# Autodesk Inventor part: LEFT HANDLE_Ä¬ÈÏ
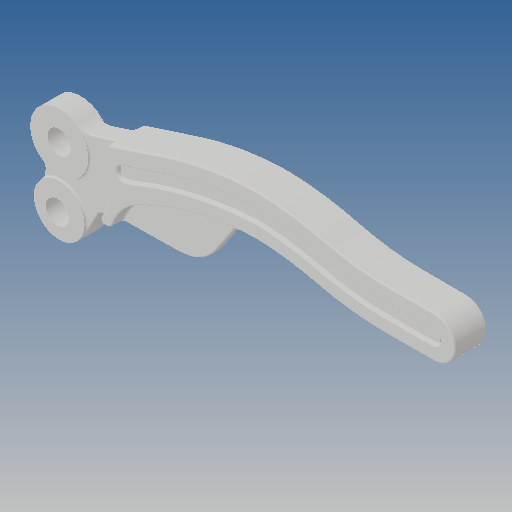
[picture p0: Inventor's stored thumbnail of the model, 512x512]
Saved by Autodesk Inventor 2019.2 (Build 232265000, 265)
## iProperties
Created: 2010-06
Part Number: LEFT HANDLE_Ä¬ÈÏ
Material: Ogólny
Document SubType Name: Modeling
Designer: CADENGINEERING4
Density: 1 g/cm^3
Appearance: Domyślna
Author: CADENGINEERING4
Revision Number: ÈÎºÎ
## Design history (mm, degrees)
feature "NONE"
node "Bryła1"
